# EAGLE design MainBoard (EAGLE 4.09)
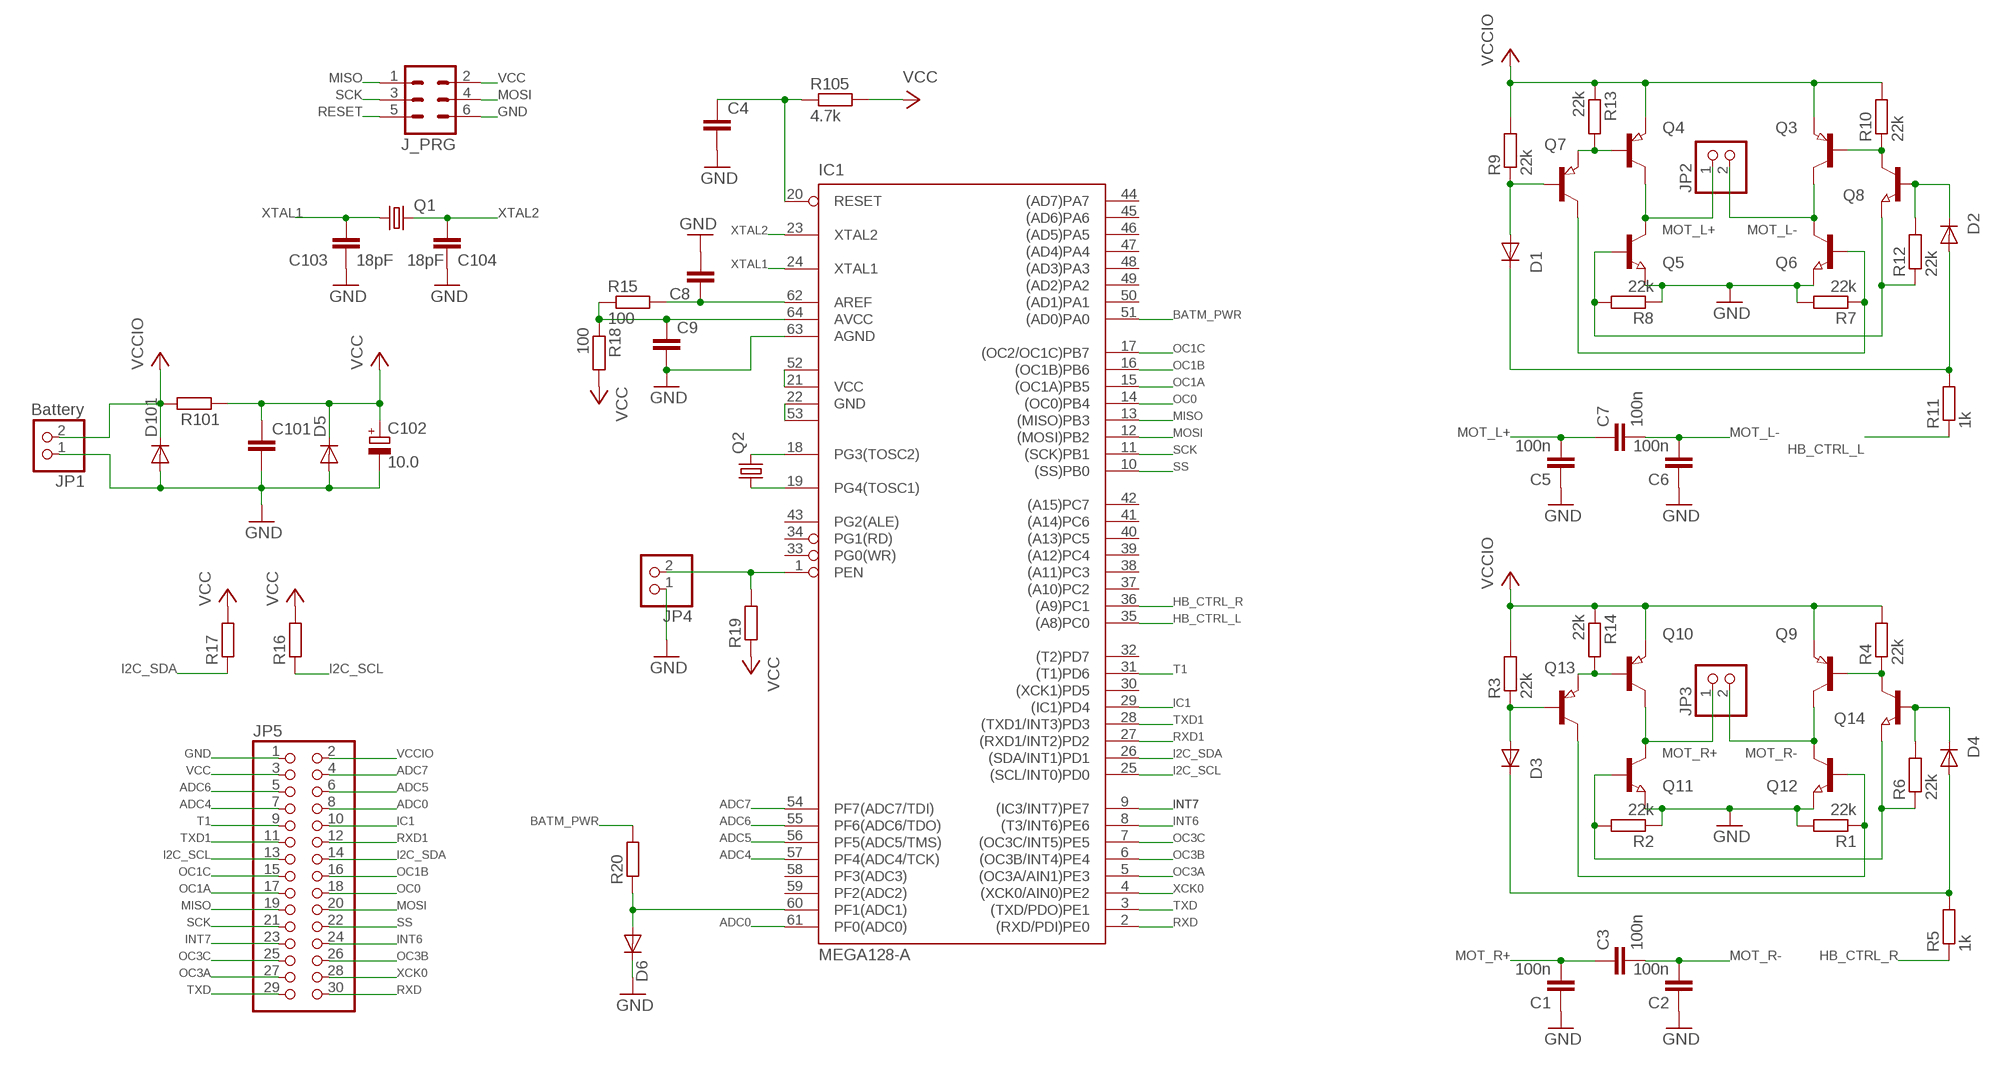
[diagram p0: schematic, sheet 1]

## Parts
C1  100n  C-EUC0805  [C0805]
C2  100n  C-EUC0805  [C0805]
C3  100n  C-EUC0805  [C0805]
C4  C-EUC0805  [C0805]
C5  100n  C-EUC0805  [C0805]
C6  100n  C-EUC0805  [C0805]
C7  100n  C-EUC0805  [C0805]
C8  C-EUC0805  [C0805]
C9  C-EUC0805  [C0805]
C101  C-EUC1206  [C1206]
C102  10.0  CPOL-EU085CS-1AR  [085CS_1AR]
C103  18pF  C-EUC0805  [C0805]
C104  18pF  C-EUC0805  [C0805]
D1  PMLL4150  [SOD80C]
D2  PMLL4150  [SOD80C]
D3  PMLL4150  [SOD80C]
D4  PMLL4150  [SOD80C]
D5  PMLL4150  [SOD80C]
D6  PMLL4150  [SOD80C]
D101  PMLL4150  [SOD80C]
IC1  MEGA128-A  [TQFP64]
J_PRG  MA03-2  [MA03-2]
JP1  Battery  PINHD-1X2  [1X02]
JP2  PINHD-1X2  [1X02]
JP3  PINHD-1X2  [1X02]
JP4  PINHD-1X2  [1X02]
JP5  PINHD-2X15  [2X15]
Q1  CRYTALHC49S  [HC49/S]
Q2  CRYTALTC26H  [TC26H]
Q3  PNP-TRANSISTOR_SOT23  [SOT23]
Q4  PNP-TRANSISTOR_SOT23  [SOT23]
Q5  NPN-TRANSISTOR_SOT23  [SOT23]
Q6  NPN-TRANSISTOR_SOT23  [SOT23]
Q7  PNP-TRANSISTOR_SOT23  [SOT23]
Q8  NPN-TRANSISTOR_SOT23  [SOT23]
Q9  PNP-TRANSISTOR_SOT23  [SOT23]
Q10  PNP-TRANSISTOR_SOT23  [SOT23]
Q11  NPN-TRANSISTOR_SOT23  [SOT23]
Q12  NPN-TRANSISTOR_SOT23  [SOT23]
Q13  PNP-TRANSISTOR_SOT23  [SOT23]
Q14  NPN-TRANSISTOR_SOT23  [SOT23]
R1  22k  R-EU_M0805  [M0805]
R2  22k  R-EU_M0805  [M0805]
R3  22k  R-EU_M0805  [M0805]
R4  22k  R-EU_M0805  [M0805]
R5  1k  R-EU_M0805  [M0805]
R6  22k  R-EU_M0805  [M0805]
R7  22k  R-EU_M0805  [M0805]
R8  22k  R-EU_M0805  [M0805]
R9  22k  R-EU_M0805  [M0805]
R10  22k  R-EU_M0805  [M0805]
R11  1k  R-EU_M0805  [M0805]
R12  22k  R-EU_M0805  [M0805]
R13  22k  R-EU_M0805  [M0805]
R14  22k  R-EU_M0805  [M0805]
R15  100  R-EU_M0805  [M0805]
R16  R-EU_R0805  [R0805]
R17  R-EU_R0805  [R0805]
R18  100  R-EU_M0805  [M0805]
R19  R-EU_R0805  [R0805]
R20  R-EU_R0805  [R0805]
R101  R-EU_M1206  [M1206]
R105  4.7k  R-EU_M0805  [M0805]

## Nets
ADC0: IC1.61(PF0(ADC0)) JP5.8
ADC4: IC1.57(PF4(ADC4/TCK)) JP5.7
ADC5: IC1.56(PF5(ADC5/TMS)) JP5.6
ADC6: IC1.55(PF6(ADC6/TDO)) JP5.5
ADC7: IC1.54(PF7(ADC7/TDI)) JP5.4
BATM_PWR: IC1.51((AD0)PA0) R20.2
GND [GND]: C1.1 C2.1 C4.2 C5.1 C6.1 C8.2 C9.2 C101.2 C102.- C103.2 C104.2 D5.A D6.C D101.A IC1.22(GND) IC1.53(GND1) IC1.63(AGND) J_PRG.6 JP1.1 JP4.1 JP5.1 Q5.2(E) Q6.2(E) Q11.2(E) Q12.2(E) R1.2 R2.1 R7.2 R8.1
HB_CTRL_L: IC1.35((A8)PC0) R11.1
HB_CTRL_R: IC1.36((A9)PC1) R5.1
I2C_SCL: IC1.25((SCL/INT0)PD0) JP5.13 R16.1
I2C_SDA: IC1.26((SDA/INT1)PD1) JP5.14 R17.1
IC1: IC1.29((IC1)PD4) JP5.10
INT6: IC1.8((T3/INT6)PE6) JP5.24
INT7: IC1.9((IC3/INT7)PE7) JP5.23
MISO: IC1.13((MISO)PB3) J_PRG.1 JP5.19
MOSI: IC1.12((MOSI)PB2) J_PRG.4 JP5.20
MOT_L+: C5.2 C7.1 JP2.1 Q4.3(C) Q5.3(C)
MOT_L-: C6.2 C7.2 JP2.2 Q3.3(C) Q6.3(C)
MOT_R+: C1.2 C3.1 JP3.1 Q10.3(C) Q11.3(C)
MOT_R-: C2.2 C3.2 JP3.2 Q9.3(C) Q12.3(C)
N$1: C8.1 IC1.62(AREF) R15.2
N$2: D2.C Q8.1(B) R12.2
N$3: IC1.1(PEN) JP4.2 R19.2
N$4: Q10.1(B) Q13.2(E) R14.2
N$5: Q9.1(B) Q14.3(C) R4.1
N$6: Q12.1(B) Q13.3(C) R1.1
N$7: D1.A Q7.1(B) R9.1
N$8: Q4.1(B) Q7.2(E) R13.2
N$9: Q3.1(B) Q8.3(C) R10.1
N$10: Q6.1(B) Q7.3(C) R7.1
N$11: Q5.1(B) Q8.2(E) R8.2 R12.1
N$12: Q11.1(B) Q14.2(E) R2.2 R6.1
N$13: D3.A Q13.1(B) R3.1
N$14: D1.C D2.A R11.2
N$15: D3.C D4.A R5.2
N$16: D4.C Q14.1(B) R6.2
N$17: IC1.18(PG3(TOSC2)) Q2.2
N$18: IC1.19(PG4(TOSC1)) Q2.1
N$19: C9.1 IC1.64(AVCC) R15.1 R18.1
N$21: D6.A IC1.60(PF1(ADC1)) R20.1
OC0: IC1.14((OC0)PB4) JP5.18
OC1A: IC1.15((OC1A)PB5) JP5.17
OC1B: IC1.16((OC1B)PB6) JP5.16
OC1C: IC1.17((OC2/OC1C)PB7) JP5.15
OC3A: IC1.5((OC3A/AIN1)PE3) JP5.27
OC3B: IC1.6((OC3B/INT4)PE4) JP5.26
OC3C: IC1.7((OC3C/INT5)PE5) JP5.25
RESET: C4.1 IC1.20(RESET) J_PRG.5 R105.1
RXD: IC1.2((RXD/PDI)PE0) JP5.30
RXD1: IC1.27((RXD1/INT2)PD2) JP5.12
SCK: IC1.11((SCK)PB1) J_PRG.3 JP5.21
SS: IC1.10((SS)PB0) JP5.22
T1: IC1.31((T1)PD6) JP5.9
TXD: IC1.3((TXD/PDO)PE1) JP5.29
TXD1: IC1.28((TXD1/INT3)PD3) JP5.11
VCC: C101.1 C102.+ D5.C IC1.21(VCC) IC1.52(VCC1) J_PRG.2 JP5.3 R16.2 R17.2 R18.2 R19.1 R101.1 R105.2
VCCIO: D101.C JP1.2 JP5.2 Q3.2(E) Q4.2(E) Q9.2(E) Q10.2(E) R3.2 R4.2 R9.2 R10.2 R13.1 R14.1 R101.2
XCK0: IC1.4((XCK0/AIN0)PE2) JP5.28
XTAL1: C103.1 IC1.24(XTAL1) Q1.1
XTAL2: C104.1 IC1.23(XTAL2) Q1.2
Unconnected: IC1.30((XCK1)PD5) IC1.32((T2)PD7) IC1.33(PG0(WR)) IC1.34(PG1(RD)) IC1.37((A10)PC2) IC1.38((A11)PC3) IC1.39((A12)PC4) IC1.40((A13)PC5) IC1.41((A14)PC6) IC1.42((A15)PC7) IC1.43(PG2(ALE)) IC1.44((AD7)PA7) IC1.45((AD6)PA6) IC1.46((AD5)PA5) IC1.47((AD4)PA4) IC1.48((AD3)PA3) IC1.49((AD2)PA2) IC1.50((AD1)PA1) IC1.58(PF3(ADC3)) IC1.59(PF2(ADC2))

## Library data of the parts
C1-C9 C101 C103 C104 = rcl:C-EU: CAPACITOR, European symbol
C102 = rcl:CPOL-EU: POLARIZED CAPACITOR, European symbol
D1-D6 D101 = diode:PMLL4150: DIODE
IC1 = avr:MEGA128: MICROCONTROLLER 128 Kbytes FLASH 4 Kbytes SRAM 4 Kbytes EEPROM DUAL USART 8-channel 10 bit ADC
J_PRG = con-lstb:MA03-2: PIN HEADER
JP1-JP4 = pinhead:PINHD-1X2: PIN HEADER
JP5 = pinhead:PINHD-2X15: PIN HEADER
Q1 Q2 = crystal:CRYTAL: CRYSTAL
Q3 Q4 Q7 Q9 Q10 Q13 = semicon-smd-ipc:PNP-TRANSISTOR_: PNP TRANSISTOR
Q5 Q6 Q8 Q11 Q12 Q14 = semicon-smd-ipc:NPN-TRANSISTOR_: NPN TRANSISTOR
R1-R20 R101 R105 = rcl:R-EU_: RESISTOR, European symbol

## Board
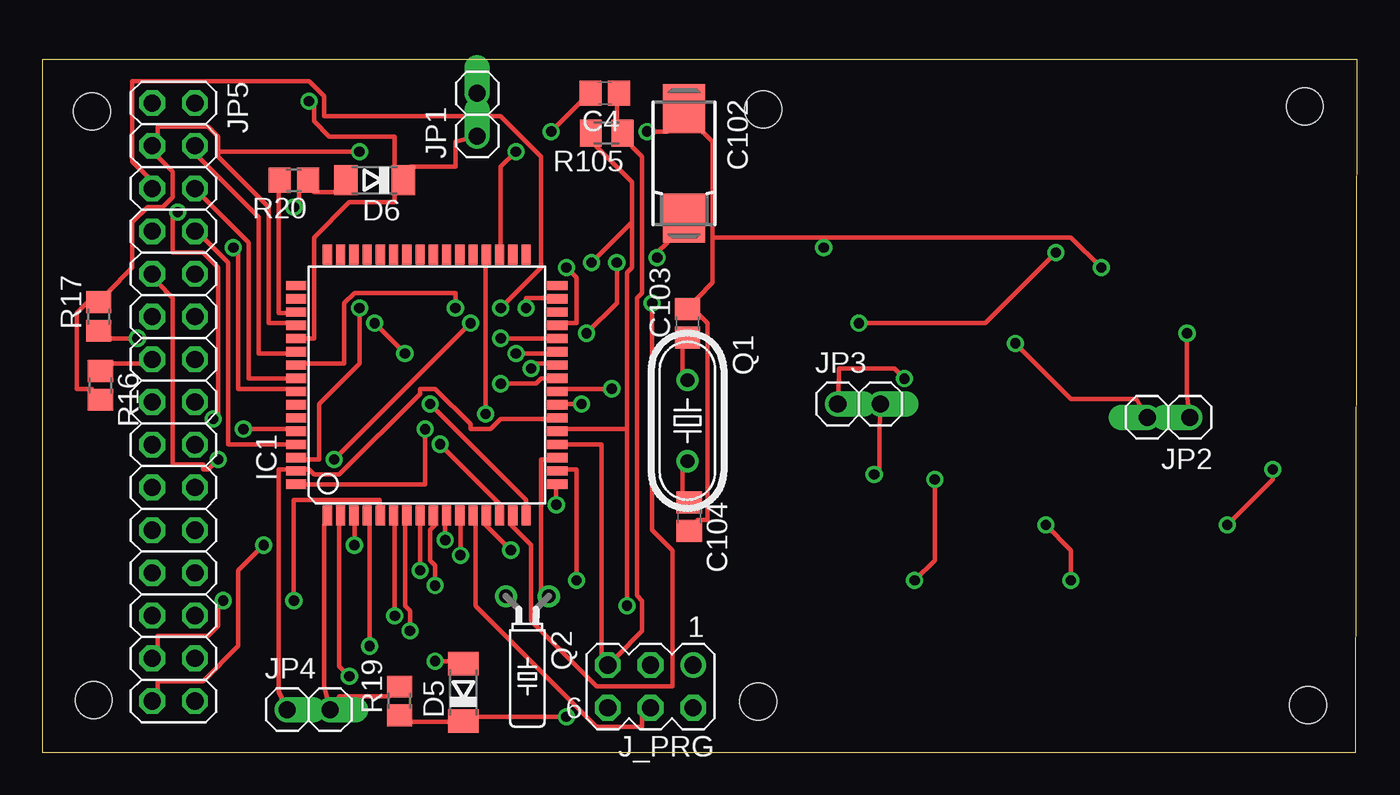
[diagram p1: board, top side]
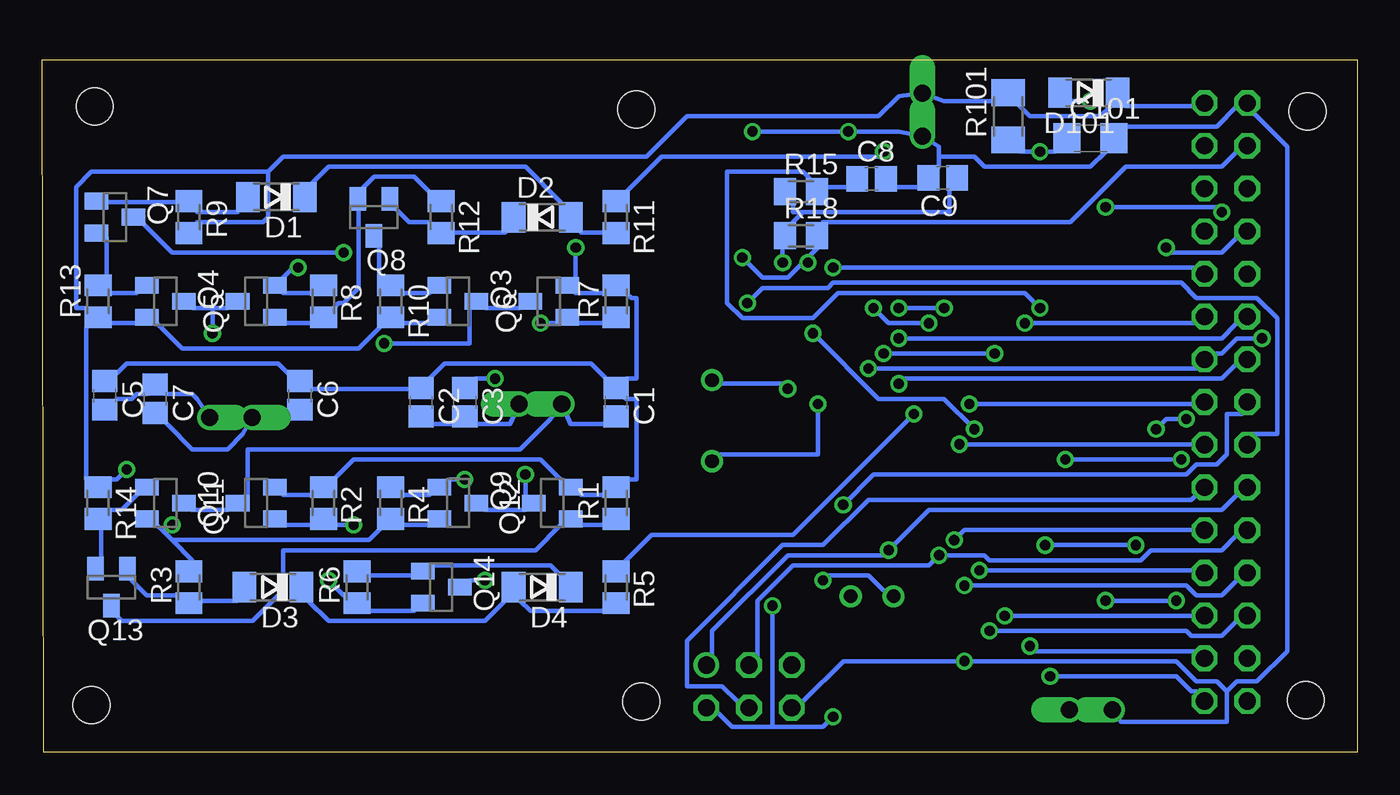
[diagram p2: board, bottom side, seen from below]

Size 78.2 x 41.2 mm. Coordinates in mm from the lower left corner, seen from the top.
Outline: 0,0 78.1,0 78.2,41.2 0,41.2 0,0
Copper layers used: Top, Bottom
Holes 2.18 mm at 75.27,2.83 75.07,38.43 42.87,38.23 42.57,3.03 2.97,38.13 3.07,3.13

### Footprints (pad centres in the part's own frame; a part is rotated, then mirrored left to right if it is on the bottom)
C0805 = smd 1.3 x 1.5: 1 -0.85,0; 2 0.85,0
C1206 = smd 1.6 x 1.8: 1 -1.4,0; 2 1.4,0
085CS_1AR = smd 2.9 x 2.5: + 3.25,0; - -3.25,0
SOD80C = smd 1.4 x 1.8: A 1.7,0; C -1.7,0
TQFP64 = smd 1.194 x 0.559: 1 -7.76,5.905; 2 -7.76,5.118; 3 -7.76,4.331; 4 -7.76,3.543; 5 -7.76,2.756; 6 -7.76,1.968; 7 -7.76,1.181; 8 -7.76,0.394; 9 -7.76,-0.394; 10 -7.76,-1.181; 11 -7.76,-1.968; 12 -7.76,-2.756; 13 -7.76,-3.543; 14 -7.76,-4.331; 15 -7.76,-5.118; 16 -7.76,-5.905; 33 7.76,-5.905; 34 7.76,-5.118; 35 7.76,-4.331; 36 7.76,-3.543; 37 7.76,-2.756; 38 7.76,-1.968; 39 7.76,-1.181; 40 7.76,-0.394; 41 7.76,0.394; 42 7.76,1.181; 43 7.76,1.968; 44 7.76,2.756; 45 7.76,3.543; 46 7.76,4.331; 47 7.76,5.118; 48 7.76,5.905 | smd 0.559 x 1.194: 17 -5.905,-7.76; 18 -5.118,-7.76; 19 -4.331,-7.76; 20 -3.543,-7.76; 21 -2.756,-7.76; 22 -1.968,-7.76; 23 -1.181,-7.76; 24 -0.394,-7.76; 25 0.394,-7.76; 26 1.181,-7.76; 27 1.968,-7.76; 28 2.756,-7.76; 29 3.543,-7.76; 30 4.331,-7.76; 31 5.118,-7.76; 32 5.905,-7.76; 49 5.905,7.76; 50 5.118,7.76; 51 4.331,7.76; 52 3.543,7.76; 53 2.756,7.76; 54 1.968,7.76; 55 1.181,7.76; 56 0.394,7.76; 57 -0.394,7.76; 58 -1.181,7.76; 59 -1.968,7.76; 60 -2.756,7.76; 61 -3.543,7.76; 62 -4.331,7.76; 63 -5.118,7.76; 64 -5.905,7.76
MA03-2 = drill 1.016 round: 1 -2.54,-1.27 | drill 1.016 octagon: 2 -2.54,1.27; 3 0,-1.27; 4 0,1.27; 5 2.54,-1.27; 6 2.54,1.27
1X02 = drill 1.016 offset: 1 -1.27,0; 2 1.27,0
2X15 = drill 1.016 octagon: 1 -17.78,-1.27; 2 -17.78,1.27; 3 -15.24,-1.27; 4 -15.24,1.27; 5 -12.7,-1.27; 6 -12.7,1.27; 7 -10.16,-1.27; 8 -10.16,1.27; 9 -7.62,-1.27; 10 -7.62,1.27; 11 -5.08,-1.27; 12 -5.08,1.27; 13 -2.54,-1.27; 14 -2.54,1.27; 15 0,-1.27; 16 0,1.27; 17 2.54,-1.27; 18 2.54,1.27; 19 5.08,-1.27; 20 5.08,1.27; 21 7.62,-1.27; 22 7.62,1.27; 23 10.16,-1.27; 24 10.16,1.27; 25 12.7,-1.27; 26 12.7,1.27; 27 15.24,-1.27; 28 15.24,1.27; 29 17.78,-1.27; 30 17.78,1.27
HC49/S = drill 0.813 round: 1 -2.413,0; 2 2.413,0
TC26H = drill 0.813 round: 1 -1.27,0; 2 1.27,0
SOT23 = smd 1 x 1.4: 1 -0.95,-1.1; 2 0.95,-1.1; 3 0,1.1
M0805 = smd 1.3 x 1.6: 1 -0.95,0; 2 0.95,0
R0805 = smd 1.3 x 1.5: 1 -0.85,0; 2 0.85,0
M1206 = smd 1.6 x 2: 1 -1.4,0; 2 1.4,0

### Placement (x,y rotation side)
C1  44.07,20.83 270 bottom
C2  55.67,20.83 270 bottom
C3  53.07,20.83 270 bottom
C4  33.46,39.21 180 top
C5  74.47,21.23 270 bottom
C6  62.87,21.23 270 bottom
C7  71.47,21.03 270 bottom
C8  28.89,34.11 0 bottom
C9  24.65,34.17 180 bottom
C101  15.87,36.53 0 bottom
C102  38.17,35.03 270 top
C103  38.37,25.53 90 top
C104  38.47,14.03 270 top
D1  64.27,33.03 180 bottom
D2  48.47,31.83 0 bottom
D3  64.47,9.83 180 bottom
D4  48.47,9.83 180 bottom
D5  25.05,3.58 90 top
D6  19.77,34.03 180 top
D101  15.97,39.23 180 bottom
IC1  22.87,21.86 90 top
J_PRG  36.17,3.93 180 top
JP1  25.87,37.93 90 top
JP2  66.97,19.93 180 top
JP3  48.57,20.73 0 top
JP4  15.85,2.55 0 top
JP5  7.82,20.84 270 top
Q1  38.37,19.73 270 top
Q2  28.85,9.29 180 top
Q3  53.47,26.83 270 bottom
Q4  70.87,26.83 270 bottom
Q5  65.47,26.83 90 bottom
Q6  48.07,26.83 90 bottom
Q7  73.87,31.83 270 bottom
Q8  58.47,31.83 180 bottom
Q9  53.47,14.83 270 bottom
Q10  70.87,14.83 270 bottom
Q11  65.47,14.83 90 bottom
Q12  47.87,14.83 90 bottom
Q13  74.07,9.83 180 bottom
Q14  54.47,9.83 270 bottom
R1  44.07,14.83 90 bottom
R2  61.47,14.83 270 bottom
R3  69.47,9.83 90 bottom
R4  57.47,14.83 270 bottom
R5  44.07,9.83 270 bottom
R6  59.47,9.83 90 bottom
R7  44.07,26.83 90 bottom
R8  61.47,26.83 270 bottom
R9  69.47,31.83 270 bottom
R10  57.47,26.83 270 bottom
R11  44.07,31.83 270 bottom
R12  54.47,31.83 270 bottom
R13  74.87,26.83 90 bottom
R14  74.87,14.83 270 bottom
R15  33.09,33.35 0 bottom
R16  3.47,21.83 270 top
R17  3.37,25.93 90 top
R18  33.09,30.73 0 bottom
R19  21.25,3.07 90 top
R20  14.97,34.03 180 top
R101  20.77,37.83 90 bottom
R105  33.57,36.83 180 top

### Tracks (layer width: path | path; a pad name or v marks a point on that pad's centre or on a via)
ADC0
  Top 0.254: IC1.61 14.67,18.33 11.07,18.33 11.07,29.13 9.57,30.63 JP5.8
ADC4  (via drill 0.61)
  Top 0.254: v11.37,30.03 11.67,29.73 11.67,21.63 14.67,21.63 IC1.57
  Bottom 0.254: v11.37,30.03 11.07,29.73 8.07,29.73 7.17,30.63 JP5.7
ADC5
  Top 0.254: IC1.56 14.67,22.23 12.27,22.23 12.27,30.33 9.57,33.03 JP5.6
ADC6  (via drill 0.61)
  Top 0.254: v24.57,26.43 24.57,27.33 18.57,27.33 17.97,26.73 17.97,23.13 15.57,23.13 IC1.55 | v27.27,26.43 29.67,28.83 29.67,35.43 27.27,37.83 16.77,37.83 16.77,39.03 15.87,39.93 5.37,39.93 5.37,35.13 6.27,34.23 JP5.5
  Bottom 0.254: v24.57,26.43 v27.27,26.43
ADC7
  Top 0.254: IC1.54 14.67,23.73 12.87,23.73 12.87,31.83 9.27,35.43 JP5.4
BATM_PWR
  Top 0.254: IC1.51 14.67,26.13 14.07,26.13 14.07,33.33 R20.2
GND  (via drill 0.61)
  Top 0.254: JP4.1 14.07,3.63 14.07,16.83 14.67,16.83 IC1.63 15.57,16.83 15.87,16.83 16.17,16.53 17.67,16.53 22.47,21.33 22.47,21.63 23.37,21.63 25.47,19.53 25.47,19.23 26.67,19.23 27.27,19.83 30.27,19.83 IC1.22 | v23.37,5.43 24.27,5.43 D5.A | IC1.53 15.57,24.63 16.17,24.63 16.17,30.63 18.27,32.73 20.97,32.73 20.97,33.33 D6.C | v15.87,38.73 16.17,38.43 16.17,37.53 17.07,36.63 20.97,36.63 20.97,34.83 D6.C | v30.27,36.93 32.07,38.73 C4.2 | D6.C 21.87,34.83 24.57,34.83 24.57,36.33 JP1.1 | C104.2 38.97,13.83 39.57,13.83 39.57,25.53 38.97,26.13 C103.2 38.97,27.03 39.87,27.93 39.87,30.63 | 39.87,30.63 39.87,36.33 39.27,36.93 C102.- 37.17,36.93 v35.97,36.93 | v62.97,28.83 61.17,30.63 46.47,30.63 | 39.87,30.63 46.47,30.63 | 46.47,30.63 v46.47,30.03
  Bottom 0.254: 7.77,3.63 8.37,4.23 9.57,4.23 10.77,5.43 v23.37,5.43 30.57,5.43 32.97,3.03 J_PRG.6 | 7.77,3.63 7.77,1.83 14.07,1.83 JP4.1 | C5.1 73.77,22.53 73.17,23.13 64.17,23.13 63.57,22.53 C6.1 62.37,21.63 56.37,21.63 C2.1 55.17,22.23 54.27,23.13 45.57,23.13 44.67,22.23 C1.1 | Q11.2 63.87,15.33 62.07,15.33 R2.1 60.87,16.23 59.67,17.43 48.57,17.43 47.37,16.23 Q12.2 46.17,15.33 44.67,15.33 R1.2 43.47,16.23 42.87,16.23 42.87,21.03 43.47,21.03 C1.1 | C1.1 43.47,22.23 42.87,22.23 42.87,27.03 43.17,27.03 43.47,27.33 R7.2 44.67,27.33 46.47,27.33 Q6.2 46.47,28.23 v46.47,30.03 | v15.87,38.73 17.07,38.73 D101.A | 24.87,35.43 24.87,36.03 JP1.1 27.27,36.93 v30.27,36.93 v35.97,36.93 | 24.87,35.43 24.87,34.83 C9.2 26.07,33.63 27.57,33.63 C8.2 | 24.87,35.43 22.77,35.43 22.17,34.83 15.87,34.83 14.97,35.73 C101.2 13.77,37.23 8.37,37.23 7.17,38.43 JP5.1 6.27,38.13 4.17,36.03 4.17,6.03 5.97,4.23 7.17,4.23 7.77,3.63 | R8.1 62.07,27.33 63.87,27.33 Q5.2 63.87,28.23 63.27,28.83 v62.97,28.83
HB_CTRL_L  (via drill 0.61)
  Top 0.254: v28.17,35.73 27.27,34.83 27.27,30.03 IC1.35
  Bottom 0.254: v28.17,35.73 28.47,35.43 41.37,35.43 43.47,33.33 R11.1
HB_CTRL_R  (via drill 0.61)
  Top 0.254: v26.37,20.13 26.37,29.13 IC1.36
  Bottom 0.254: v26.37,20.13 33.57,12.93 41.97,12.93 43.47,11.43 R5.1
I2C_SCL  (via drill 0.61)
  Top 0.254: v27.27,21.93 29.37,21.93 29.67,22.23 30.27,22.23 IC1.25 | R16.1 4.17,23.13 5.97,23.13 JP5.13
  Bottom 0.254: v27.27,21.93 26.97,22.23 8.07,22.23 7.17,23.13 JP5.13
I2C_SDA  (via drill 0.61)
  Top 0.254: v29.07,22.83 29.07,23.13 30.27,23.13 IC1.26 | v5.67,24.63 3.87,24.63 R17.1
  Bottom 0.254: v29.07,22.83 9.57,22.83 JP5.14 8.37,23.73 8.07,23.73 7.17,24.63 v5.67,24.63
IC1  (via drill 0.61)
  Top 0.254: v31.17,28.83 31.77,28.23 31.77,25.53 31.17,25.53 IC1.29
  Bottom 0.254: v31.17,28.83 9.57,28.83 JP5.10
INT6  (via drill 0.61)
  Top 0.254: v22.47,10.83 22.47,13.53 IC1.8
  Bottom 0.254: v22.47,10.83 9.57,10.83 JP5.24
INT7  (via drill 0.61)
  Top 0.254: v23.37,9.93 23.37,11.13 23.07,11.43 23.07,13.23 23.37,13.53 IC1.9
  Bottom 0.254: v23.37,9.93 10.17,9.93 9.57,9.33 8.07,9.33 7.17,10.23 JP5.23
MISO  (via drill 0.61)
  Top 0.254: v27.87,12.03 26.37,13.53 IC1.13
  Bottom 0.254: J_PRG.1 38.37,5.73 38.37,7.23 33.87,11.73 28.17,11.73 v27.87,12.03 25.47,14.43 8.07,14.43 7.17,15.33 JP5.19
MOSI
  Top 0.254: IC1.12 25.77,13.53 25.77,8.73 32.97,1.53 35.67,1.53 35.67,2.13 J_PRG.4
  Bottom 0.254: JP5.20 9.57,15.33 9.87,15.03 29.07,15.03 31.77,12.33 34.17,12.33 39.87,6.63 39.87,3.93 37.77,3.93 36.87,3.03 J_PRG.4
MOT_L+  (via drill 0.61)
  Top 0.254: v68.07,24.93 68.07,21.33 JP2.1
  Bottom 0.254: 68.07,26.43 69.27,26.43 Q4.3 | 68.07,26.43 67.17,26.43 Q5.3 | C5.2 73.77,21.03 72.87,21.03 72.57,21.33 71.97,21.33 C7.1 70.77,21.33 69.27,21.33 68.97,21.03 JP2.1 | v68.07,24.93 68.07,26.43
MOT_L-  (via drill 0.61)
  Top 0.254: v57.87,24.33 61.17,21.03 65.07,21.03 JP2.2
  Bottom 0.254: Q6.3 49.77,26.43 51.87,26.43 Q3.3 52.77,26.43 52.77,24.33 v57.87,24.33 | C6.2 63.57,19.83 65.07,19.83 JP2.2 66.27,18.93 67.17,18.03 69.27,18.03 70.77,19.53 C7.2
MOT_R+  (via drill 0.61)
  Top 0.254: v51.27,22.23 50.67,22.83 47.37,22.83 47.37,22.23 JP3.1
  Bottom 0.254: Q10.3 69.27,14.43 67.17,14.43 Q11.3 65.97,15.33 65.97,18.03 49.77,18.03 47.97,19.83 JP3.1 46.77,19.53 44.67,19.53 C1.2 | v51.27,22.23 52.47,22.23 C3.1
MOT_R-  (via drill 0.61)
  Top 0.254: v49.47,16.53 49.77,16.83 49.77,19.23 JP3.2
  Bottom 0.254: Q9.3 51.87,14.43 49.47,14.43 Q12.3 49.47,15.33 v49.47,16.53 | C2.2 55.17,19.53 53.67,19.53 C3.2 52.47,19.53 50.37,19.53 JP3.2
N$1  (via drill 0.61)
  Top 0.254: v18.87,26.43 18.87,23.13 16.47,20.73 16.47,17.43 15.57,17.43 IC1.62
  Bottom 0.254: v18.87,26.43 19.77,27.33 30.87,27.33 32.37,25.83 36.57,25.83 37.47,26.73 37.47,34.53 32.97,34.53 32.37,33.93 R15.2 31.77,33.63 30.27,33.63 C8.1
N$2
  Bottom 0.254: Q8.1 57.27,32.43 56.37,31.53 55.17,31.53 R12.2 53.97,30.93 50.67,30.93 D2.C
N$3
  Top 0.254: IC1.1 16.77,13.53 16.77,3.93 JP4.2 17.67,3.33 20.67,3.33 R19.2
N$4
  Bottom 0.254: Q13.2 74.67,11.43 74.67,13.23 R14.2 74.37,14.43 73.47,14.43 72.57,15.33 Q10.1
N$5  (via drill 0.61)
  Top 0.254: v51.87,10.23 53.07,11.43 v53.07,16.23
  Bottom 0.254: v51.87,10.23 52.77,10.23 Q14.3 | v53.07,16.23 53.97,16.23 Q9.1 55.17,15.33 56.97,15.33 R4.1
N$6
  Bottom 0.254: R1.1 44.67,13.53 46.17,13.53 Q12.1 47.37,13.53 48.87,12.03 63.87,12.03 63.87,9.63 65.67,7.83 73.47,7.83 73.77,8.13 Q13.3
N$7
  Bottom 0.254: Q7.1 74.37,32.73 70.17,32.73 R9.1 68.97,32.13 66.57,32.13 D1.A
N$8
  Bottom 0.254: Q4.1 72.57,27.33 74.37,27.33 R13.2 74.37,28.23 74.37,30.63 Q7.2
N$9
  Bottom 0.254: Q3.1 55.17,27.33 56.97,27.33 R10.1 58.17,28.23 58.17,30.03 Q8.3
N$10  (via drill 0.61)
  Top 0.254: v60.27,29.73 56.07,25.53 v48.57,25.53
  Bottom 0.254: R7.1 44.67,25.53 46.47,25.53 Q6.1 47.37,25.53 v48.57,25.53 | v60.27,29.73 70.47,29.73 72.27,31.53 Q7.3
N$11
  Bottom 0.254: Q5.1 63.87,25.53 62.07,25.53 R8.2 60.87,26.43 60.57,26.73 60.27,26.73 59.37,27.63 59.37,32.43 Q8.2 59.07,33.63 58.47,34.23 56.07,34.23 55.17,33.33 R12.1
N$12  (via drill 0.61)
  Top 0.254: v59.67,13.53 61.17,12.03 v61.17,10.23
  Bottom 0.254: Q11.1 63.87,13.53 62.07,13.53 R2.2 60.87,13.53 v59.67,13.53 | Q14.2 56.07,8.43 58.77,8.43 R6.1 59.97,9.33 60.27,9.33 v61.17,10.23
N$13
  Bottom 0.254: Q13.1 72.87,10.23 71.97,9.33 70.17,9.33 R3.1 68.97,9.03 66.57,9.03 D3.A
N$14
  Bottom 0.254: R11.2 44.67,30.93 46.17,30.93 D2.A 47.37,32.73 49.47,34.83 61.17,34.83 62.07,33.93 D1.C
N$15
  Bottom 0.254: R5.2 44.67,8.43 49.17,8.43 49.77,9.03 D4.A 50.67,9.03 51.87,7.83 61.17,7.83 62.37,9.03 D3.C
N$16
  Bottom 0.254: R6.2 58.77,10.53 56.07,10.53 Q14.1 55.17,11.13 47.97,11.13 47.37,10.53 D4.C
N$17  (via drill 0.61)
  Top 0.254: v31.77,10.23 31.77,16.83 31.17,16.83 IC1.18
  Bottom 0.254: v31.77,10.23 31.47,10.53 29.07,10.53 28.17,9.63 Q2.2
N$18
  Top 0.254: IC1.19 30.27,17.43 29.67,17.43 29.67,9.63 Q2.1
N$19  (via drill 0.61)
  Top 0.254: v22.77,19.23 22.77,15.93 15.57,15.93 IC1.64 | v32.37,24.93 34.17,26.73 v34.17,29.13
  Bottom 0.254: v22.77,19.23 24.57,21.03 28.47,21.03 v32.37,24.93 | v34.17,29.13 34.17,30.03 R18.1 33.57,31.53 32.97,32.13 | 32.97,32.13 24.27,32.13 24.27,33.63 C9.1 | 32.97,32.13 33.57,32.13 33.57,32.73 R15.1
N$21  (via drill 0.61)
  Top 0.254: v11.97,19.23 14.67,19.23 IC1.60 | v10.17,19.83 10.47,20.13 10.47,28.83 9.57,29.73 7.77,29.73 7.77,31.83 v8.07,32.13 | v14.97,32.43 15.27,32.73 15.27,33.33 R20.1 16.17,33.33 17.67,33.33 D6.A
  Bottom 0.254: v11.97,19.23 11.37,19.83 v10.17,19.83 | v8.07,32.13 8.37,32.43 v14.97,32.43
OC0  (via drill 0.61)
  Top 0.254: v23.67,18.33 27.27,14.73 27.27,14.43 IC1.14
  Bottom 0.254: v23.67,18.33 9.57,18.33 JP5.18
OC1A  (via drill 0.61)
  Top 0.254: v36.27,26.73 36.27,13.23 37.47,12.03 37.47,3.93 32.97,3.93 29.07,7.83 29.07,12.33 27.87,13.53 IC1.15
  Bottom 0.254: v36.27,26.73 35.37,27.63 31.47,27.63 31.17,27.93 10.47,27.93 9.57,27.03 5.97,27.03 4.77,25.83 4.77,18.93 6.27,18.93 JP5.17
OC1B  (via drill 0.61)
  Top 0.254: v23.07,20.73 28.77,15.03 28.77,14.43 IC1.16
  Bottom 0.254: v23.07,20.73 9.57,20.73 JP5.16
OC1C  (via drill 0.61)
  Top 0.254: v30.57,14.73 30.57,15.93 IC1.17
  Bottom 0.254: v30.57,14.73 28.77,16.53 10.17,16.53 9.57,17.13 8.37,17.13 7.77,17.73 7.77,20.13 6.87,20.13 JP5.15
OC3A  (via drill 0.61)
  Top 0.254: v14.97,9.03 14.97,15.03 20.07,15.03 20.07,14.43 IC1.5 | v10.77,9.03 10.47,8.73 10.47,7.53 9.87,6.93 6.87,6.93 6.87,6.33 JP5.27
  Bottom 0.254: v10.77,9.03 v14.97,9.03
OC3B  (via drill 0.61)
  Top 0.254: v20.97,8.13 20.97,13.53 IC1.6
  Bottom 0.254: v20.97,8.13 9.57,8.13 JP5.26
OC3C  (via drill 0.61)
  Top 0.254: v21.87,7.23 21.87,8.43 21.57,8.73 21.57,13.53 IC1.7
  Bottom 0.254: v21.87,7.23 10.17,7.23 9.87,6.93 8.07,6.93 7.17,7.83 JP5.25
RESET
  Top 0.254: C4.1 34.17,38.73 34.17,37.53 R105.1 35.07,36.03 35.67,35.43 35.67,27.33 35.37,27.03 35.37,9.33 35.67,9.03 35.67,7.23 34.17,5.73 J_PRG.5 33.27,5.73 33.27,18.33 31.17,18.33 IC1.20
RXD  (via drill 0.61)
  Top 0.254: v18.27,4.53 17.67,5.13 17.67,13.53 IC1.2
  Bottom 0.254: v18.27,4.53 10.77,4.53 9.87,3.63 9.57,3.63 JP5.30
RXD1  (via drill 0.61)
  Top 0.254: v28.17,23.73 30.27,23.73 IC1.27 | v19.77,25.53 v21.57,23.73
  Bottom 0.254: v21.57,23.73 v28.17,23.73 | v19.77,25.53 9.57,25.53 JP5.12
SCK  (via drill 0.61)
  Top 0.254: v24.87,11.73 24.87,13.53 IC1.11
  Bottom 0.254: J_PRG.3 35.67,5.73 35.67,9.03 33.57,11.13 25.47,11.13 v24.87,11.73 22.17,11.73 21.87,11.43 12.87,11.43 12.27,12.03 8.07,12.03 7.17,12.93 JP5.21
SS  (via drill 0.61)
  Top 0.254: v23.97,12.63 23.97,13.53 IC1.10
  Bottom 0.254: v23.97,12.63 23.37,13.23 9.57,13.23 JP5.22
T1  (via drill 0.61)
  Top 0.254: v28.77,26.43 28.77,27.03 30.27,27.03 IC1.31 | v17.37,17.43 v25.47,25.53 | v10.47,17.43 9.87,16.83 9.57,16.83 9.57,17.13 7.77,17.13 7.77,27.03 6.87,27.93 JP5.9
  Bottom 0.254: v28.77,26.43 27.87,25.53 v25.47,25.53 | v10.47,17.43 v17.37,17.43
TXD  (via drill 0.61)
  Top 0.254: v18.57,12.33 18.57,13.53 IC1.3 | v13.17,12.33 11.67,10.83 11.67,6.33 9.57,4.23 6.87,4.23 6.87,3.63 JP5.29
  Bottom 0.254: v13.17,12.33 v18.57,12.33
TXD1  (via drill 0.61)
  Top 0.254: v27.27,24.63 30.27,24.63 IC1.28
  Bottom 0.254: v27.27,24.63 8.07,24.63 7.17,25.53 JP5.11
VCC  (via drill 0.61)
  Top 0.254: R16.2 2.97,21.63 2.07,21.63 2.07,26.13 2.67,26.73 R17.2 3.87,27.33 5.37,28.83 5.37,31.53 6.27,32.43 7.17,32.43 7.77,33.03 7.77,34.53 6.87,35.43 JP5.3 6.87,36.63 6.87,37.23 9.87,37.23 10.47,36.63 10.47,35.73 | 10.47,35.73 10.47,35.43 13.47,32.43 13.47,25.53 14.67,25.53 IC1.52 | v36.57,29.43 36.57,29.73 37.17,30.33 C102.+ | 10.47,35.73 v18.87,35.73 | R19.1 21.87,1.83 24.27,1.83 D5.C 25.77,2.13 v31.17,2.13 | 34.77,19.23 31.17,19.23 IC1.21 | 34.77,19.23 34.77,28.53 35.07,28.83 35.07,31.53 | 35.07,31.53 35.07,33.93 32.97,36.03 R105.2 | v34.77,8.73 34.77,19.23 | 35.07,31.53 v32.67,29.13
  Bottom 0.254: C101.1 17.97,35.73 v18.87,35.73 20.07,35.73 R101.1 | JP5.3 7.17,35.73 8.07,34.83 13.77,34.83 17.07,31.53 31.77,31.53 R18.2 32.07,30.03 32.97,29.13 | v36.57,29.43 35.37,28.23 33.87,28.23 32.97,29.13 | 34.77,1.53 31.77,1.53 v31.17,2.13 | 34.77,1.53 37.17,1.53 38.07,2.43 J_PRG.2 | 34.77,1.53 v34.77,8.73 | v32.67,29.13 32.97,29.13
VCCIO  (via drill 0.61)
  Top 0.254: v70.47,13.53 73.17,16.23 v73.17,16.83
  Bottom 0.254: Q9.2 55.17,13.53 56.97,13.53 R4.2 58.17,13.23 58.77,12.63 70.47,12.63 | 70.47,12.63 69.27,11.43 R3.2 | 71.07,13.23 70.47,12.63 | 71.07,13.23 71.37,13.53 Q10.2 | JP5.2 9.57,38.43 13.77,38.43 D101.C 14.67,38.43 15.27,37.83 19.47,37.83 20.07,38.43 R101.2 21.57,38.73 24.57,38.73 JP1.2 27.27,39.03 28.47,37.83 39.87,37.83 42.27,35.43 63.87,35.43 64.77,34.53 | Q3.2 55.17,25.53 56.97,25.53 R10.2 58.17,25.23 59.37,24.03 69.87,24.03 71.37,25.53 Q4.2 72.57,25.53 74.37,25.53 R13.1 | 64.77,34.53 64.77,31.83 65.07,31.53 68.97,31.53 R9.2 | 64.77,34.53 75.27,34.53 76.17,33.63 76.17,26.43 75.57,26.43 R13.1 | R13.1 75.57,25.23 75.57,16.23 R14.1 74.37,16.23 73.77,16.23 v73.17,16.83 | 71.07,13.23 70.77,13.53 v70.47,13.53
XCK0  (via drill 0.61)
  Top 0.254: v19.47,6.33 19.47,13.53 IC1.4
  Bottom 0.254: v19.47,6.33 19.17,6.03 9.57,6.03 JP5.28
XTAL1  (via drill 0.61)
  Top 0.254: v33.87,21.63 31.17,21.63 IC1.24 | C103.1 38.07,24.03 38.07,22.53 Q1.1
  Bottom 0.254: v33.87,21.63 34.17,21.93 37.77,21.93 Q1.1
XTAL2  (via drill 0.61)
  Top 0.254: v32.07,20.73 31.17,20.73 IC1.23 | C104.1 38.07,15.33 38.07,16.83 Q1.2
  Bottom 0.254: v32.07,20.73 32.07,17.73 38.07,17.73 Q1.2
